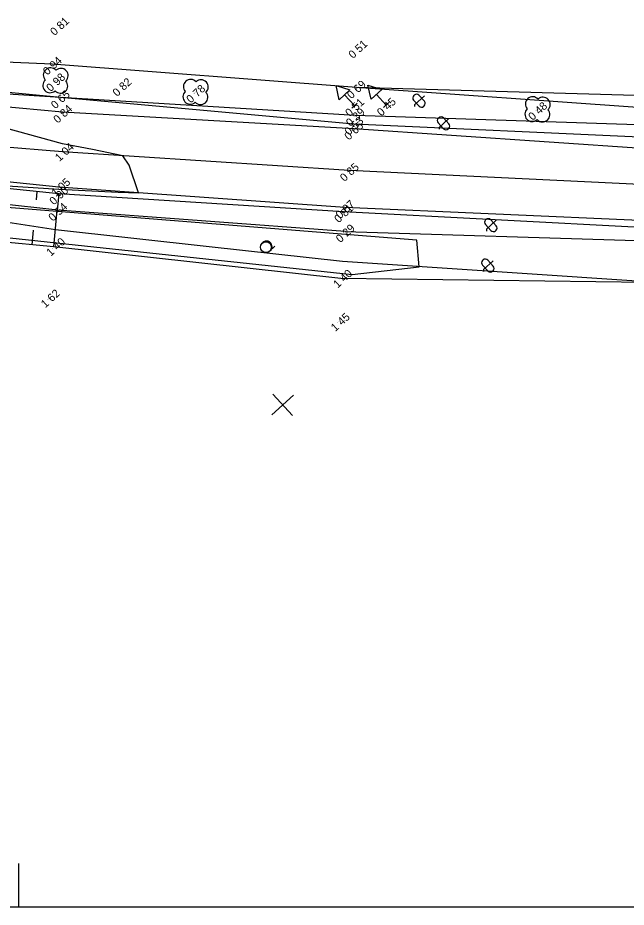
# Model space of a CAD drawing. Extents: x -740053 to -737481, y -1033516 to -1032488.
# Drawn here: x -737692.2 to -737650.4, y -1032955.3 to -1032894.1 of the extents above; entities that cross this region are included whole.
import ezdxf

# ---------------------------------------------------------------- set-up
doc = ezdxf.new("R2010")
doc.units = 0
for name, color, linetype in [('bod-oznac', 7, 'Continuous'), ('bod-vyska', 7, 'Continuous'), ('bod-vyska100', 7, 'Continuous'), ('Contours', 7, 'Continuous'), ('ctv-sit', 7, 'Continuous'), ('dopr-zariz', 7, 'Continuous'), ('Hranice-zelene', 7, 'Continuous'), ('osa-komunikace', 7, 'Continuous'), ('Predmety bez rozlišeni', 7, 'Continuous'), ('rozhraní kultůr', 7, 'Continuous'), ('silnice', 7, 'Continuous'), ('Technické šrafy', 7, 'Continuous'), ('Terenni-hrana', 7, 'Continuous'), ('Znacky-kultury', 7, 'Continuous')]:
    doc.layers.add(name, color=color, linetype=linetype)

# ---------------------------------------------------------------- blocks, each defined once
blk = doc.blocks.new('POINT_DISPLAY')
blk.add_line((0, 0), (0, 0))
blk = doc.blocks.new('p_strom')
for centre, start, end in [((0, 1), 0, 180), ((-1, 0), 90, 270), ((1, 0), 270, 90), ((0, -1), 180, 0)]:
    blk.add_arc(centre, 1, start, end)
at = {"rotation": -180}
blk.add_blockref('POINT_DISPLAY', (0, 0), dxfattribs=at)
blk = doc.blocks.new('d_znacka')
for p, q in [((-1, 2), (0, 3.73)), ((0, 3.73), (1, 2)), ((-1, 2), (1, 2)), ((0, 0), (0, 2)), ((-0.5, 0), (0.5, 0))]:
    blk.add_line(p, q)
blk = doc.blocks.new('p_neplod')
for p, q in [((-0.82, 0), (-0.99, -0.18)), ((1, 0), (-0.82, 0)), ((-0.49, 0.56), (-0.49, -0.55)), ((0.05, 1.01), (-0.04, 1.01)), ((0.5, -0.55), (0.5, 0.56)), ((-0.04, -1), (0.05, -1))]:
    blk.add_line(p, q)
for centre, start, end in [((-0.04, 0.56), 90, 180), ((0.05, 0.56), 0, 90), ((-0.04, -0.55), 180, 270), ((0.05, -0.55), 270, 0)]:
    blk.add_arc(centre, 0.45, start, end)
blk = doc.blocks.new('p_leskro')
blk.add_line((0, -0.75), (1, -0.75))
blk.add_circle((0, 0), 0.75)
blk.add_arc((0.13, 0), 0.75, 264.8832, 95.1168)
blk = doc.blocks.new('ctvsit')
for p, q in [((0, -2), (0, 2)), ((2, 0), (-2, 0))]:
    blk.add_line(p, q)

msp = doc.modelspace()

# ---------------------------------------------------------------- linework, layer by layer
at = {"layer": 'Contours'}
for points in [[(-737698.191, -1032905.341), (-737689.343, -1032905.928), (-737685.266, -1032906.126), (-737683.882, -1032906.166), (-737684.524, -1032904.257), (-737684.942, -1032903.624), (-737687.035, -1032903.194), (-737689.086, -1032902.81), (-737700.846, -1032899.576)], [(-737648.281, -1032912.342), (-737669.875, -1032910.89), (-737679.025, -1032909.87), (-737689.564, -1032908.703), (-737702.385, -1032906.745)]]:
    msp.add_lwpolyline(points, dxfattribs=at)
at = {"layer": 'Hranice-zelene'}
msp.add_lwpolyline([(-737664.607, -1032911.252), (-737664.752, -1032909.431), (-737702.393, -1032906.426), (-737702.778, -1032908.177), (-737669.214, -1032911.771), (-737664.607, -1032911.252)], dxfattribs=at)
at = {"layer": 'osa-komunikace'}
for p, q in [((-737689.086, -1032903.356), (-737715.616, -1032901.107)), ((-737669.401, -1032904.63), (-737689.086, -1032903.356)), ((-737647.386, -1032905.706), (-737669.401, -1032904.63))]:
    msp.add_line(p, q, dxfattribs=at)
at = {"layer": 'Predmety bez rozlišeni'}
for p, q in [((-737692.097, -1032955.262), (-737692.097, -1032952.262)), ((-737692.097, -1032955.262), (-737797.097, -1032955.262)), ((-737587.097, -1032955.262), (-737692.097, -1032955.262))]:
    msp.add_line(p, q, dxfattribs=at)
at = {"layer": 'rozhraní kultůr'}
msp.add_line((-737646.173, -1032899.593), (-737668.914, -1032898.94), dxfattribs=at)
at = {"layer": 'silnice'}
for p, q in [((-737689.084, -1032900.624), (-737714.813, -1032898.331)), ((-737669.09, -1032901.777), (-737689.084, -1032900.624)), ((-737646.987, -1032903.288), (-737669.09, -1032901.777)), ((-737689.336, -1032905.773), (-737715.83, -1032903.15)), ((-737669.7, -1032907.187), (-737689.336, -1032905.773)), ((-737647.525, -1032908.156), (-737669.7, -1032907.187))]:
    msp.add_line(p, q, dxfattribs=at)
at = {"layer": 'Technické šrafy'}
for p, q in [((-737690.848, -1032906.087), (-737690.904, -1032906.639)), ((-737689.356, -1032906.239), (-737689.47, -1032907.357)), ((-737689.686, -1032909.87), (-737689.455, -1032907.358)), ((-737691.179, -1032909.733), (-737691.088, -1032908.737))]:
    msp.add_line(p, q, dxfattribs=at)
at = {"layer": 'Terenni-hrana'}
for p, q in [((-737689.801, -1032897.317), (-737714.72, -1032896.289)), ((-737689.24, -1032899.627), (-737714.803, -1032897.1)), ((-737689.24, -1032899.627), (-737715.041, -1032897.875)), ((-737668.914, -1032898.94), (-737689.801, -1032897.317)), ((-737646.404, -1032900.524), (-737668.914, -1032898.94)), ((-737669.09, -1032901.452), (-737689.24, -1032899.627)), ((-737668.994, -1032900.847), (-737689.24, -1032899.627)), ((-737646.52, -1032901.595), (-737668.994, -1032900.847)), ((-737646.846, -1032902.452), (-737669.09, -1032901.452)), ((-737689.356, -1032906.239), (-737715.86, -1032903.545)), ((-737689.424, -1032907.362), (-737715.862, -1032904.43)), ((-737669.796, -1032907.466), (-737689.356, -1032906.239)), ((-737689.686, -1032909.87), (-737715.813, -1032907.468)), ((-737669.684, -1032908.83), (-737689.424, -1032907.362)), ((-737647.842, -1032908.624), (-737669.796, -1032907.466)), ((-737669.684, -1032908.83), (-737648.055, -1032909.499)), ((-737669.982, -1032912.051), (-737689.686, -1032909.87)), ((-737648.281, -1032912.342), (-737669.982, -1032912.051))]:
    msp.add_line(p, q, dxfattribs=at)

# ---------------------------------------------------------------- block references
at = {"layer": 'bod-oznac', "rotation": 42.589429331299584}
for p in [(-737689.305, -1032894.602), (-737668.819, -1032896.176), (-737689.801, -1032897.317), (-737689.573, -1032898.452), (-737685.015, -1032898.785), (-737668.914, -1032898.94), (-737689.24, -1032899.627), (-737679.953, -1032899.239), (-737669.043, -1032900.173), (-737666.862, -1032900.137), (-737689.084, -1032900.624), (-737668.994, -1032900.847), (-737656.471, -1032900.433), (-737669.09, -1032901.452), (-737669.09, -1032901.777), (-737689.086, -1032903.356), (-737669.401, -1032904.63), (-737689.336, -1032905.773), (-737689.356, -1032906.239), (-737689.424, -1032907.362), (-737669.796, -1032907.466), (-737669.7, -1032907.187), (-737669.684, -1032908.83), (-737689.686, -1032909.87), (-737669.982, -1032912.051), (-737690.047, -1032913.408), (-737670.143, -1032915.038)]:
    msp.add_blockref('POINT_DISPLAY', p, dxfattribs=at)
at = {"layer": 'ctv-sit', "xscale": 0.49999999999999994, "yscale": 0.49999999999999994, "rotation": -137.41057066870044}
msp.add_blockref('ctvsit', (-737673.972, -1032920.744), dxfattribs=at)
at = {"layer": 'dopr-zariz', "xscale": 0.4999999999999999, "yscale": 0.49999999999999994, "rotation": 42.58942933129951}
for p in [(-737669.043, -1032900.173), (-737666.862, -1032900.137)]:
    msp.add_blockref('d_znacka', p, dxfattribs=at)
at = {"layer": 'Znacky-kultury', "yscale": 0.49999999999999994}
for name, p, xscale, rotation in [('p_strom', (-737689.573, -1032898.452), 0.4999999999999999, 42.58942933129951), ('p_strom', (-737679.953, -1032899.239), 0.4999999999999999, 42.58942933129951), ('p_neplod', (-737664.613, -1032899.843), 0.49999999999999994, 42.589429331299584), ('p_strom', (-737656.471, -1032900.433), 0.4999999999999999, 42.58942933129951), ('p_neplod', (-737662.927, -1032901.397), 0.49999999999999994, 42.589429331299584), ('p_neplod', (-737659.681, -1032908.394), 0.49999999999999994, 42.589429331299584), ('p_leskro', (-737675.125, -1032909.904), 0.49999999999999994, 42.589429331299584), ('p_neplod', (-737659.885, -1032911.171), 0.49999999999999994, 42.589429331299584)]:
    msp.add_blockref(name, p, dxfattribs=dict(at, xscale=xscale, rotation=rotation))

# ---------------------------------------------------------------- texts
at = {"layer": 'bod-vyska'}
for s, p in [('0 81', (-737689.638, -1032895.406)), ('0 51', (-737669.151, -1032896.98)), ('0 94', (-737690.134, -1032898.121)), ('0 98', (-737689.906, -1032899.256)), ('0 82', (-737685.348, -1032899.589)), ('0 69', (-737669.256, -1032899.752)), ('0 65', (-737689.583, -1032900.439)), ('0 78', (-737680.285, -1032900.043)), ('0 51', (-737669.376, -1032900.977)), ('0 45', (-737667.195, -1032900.941)), ('0 84', (-737689.417, -1032901.428)), ('0 39', (-737669.327, -1032901.651)), ('0 48', (-737656.804, -1032901.237)), ('0 53', (-737669.423, -1032902.256)), ('0 65', (-737669.432, -1032902.59)), ('1 04', (-737689.303, -1032904.053)), ('0 85', (-737669.734, -1032905.434)), ('1 05', (-737689.553, -1032906.47)), ('0 90', (-737689.689, -1032907.043)), ('0 54', (-737689.757, -1032908.165)), ('0 81', (-737670.129, -1032908.27)), ('0 87', (-737670.032, -1032907.991)), ('0 29', (-737670.017, -1032909.633)), ('1 40', (-737689.903, -1032910.568)), ('1 40', (-737670.199, -1032912.749)), ('1 62', (-737690.274, -1032914.114)), ('1 45', (-737670.36, -1032915.736))]:
    msp.add_text(s, height=0.55, rotation=42.58943, dxfattribs=at).set_placement(p)
at = {"layer": 'bod-vyska100'}
for s, p in [('250 81', (-737689.405, -1032894.739)), ('250 51', (-737668.919, -1032896.314)), ('250 94', (-737689.902, -1032897.455)), ('250 98', (-737689.673, -1032898.59)), ('250 82', (-737685.116, -1032898.923)), ('250 69', (-737669.015, -1032899.078)), ('250 65', (-737689.342, -1032899.765)), ('250 78', (-737680.053, -1032899.377)), ('250 51', (-737669.144, -1032900.31)), ('250 45', (-737666.962, -1032900.275)), ('250 84', (-737689.185, -1032900.762)), ('250 39', (-737669.094, -1032900.985)), ('250 48', (-737656.571, -1032900.57)), ('250 53', (-737669.191, -1032901.589)), ('250 65', (-737669.191, -1032901.916)), ('251 04', (-737689.181, -1032903.489)), ('250 85', (-737669.501, -1032904.768)), ('251 05', (-737689.431, -1032905.906)), ('250 90', (-737689.456, -1032906.377)), ('250 54', (-737689.525, -1032907.499)), ('250 81', (-737669.897, -1032907.603)), ('250 87', (-737669.8, -1032907.324)), ('250 29', (-737669.784, -1032908.967)), ('251 40', (-737689.781, -1032910.003)), ('251 40', (-737670.077, -1032912.184)), ('251 62', (-737690.143, -1032913.541)), ('251 45', (-737670.239, -1032915.171))]:
    msp.add_text(s, height=0.05, rotation=42.58943, dxfattribs=at).set_placement(p)

doc.saveas('drawing.dxf')
